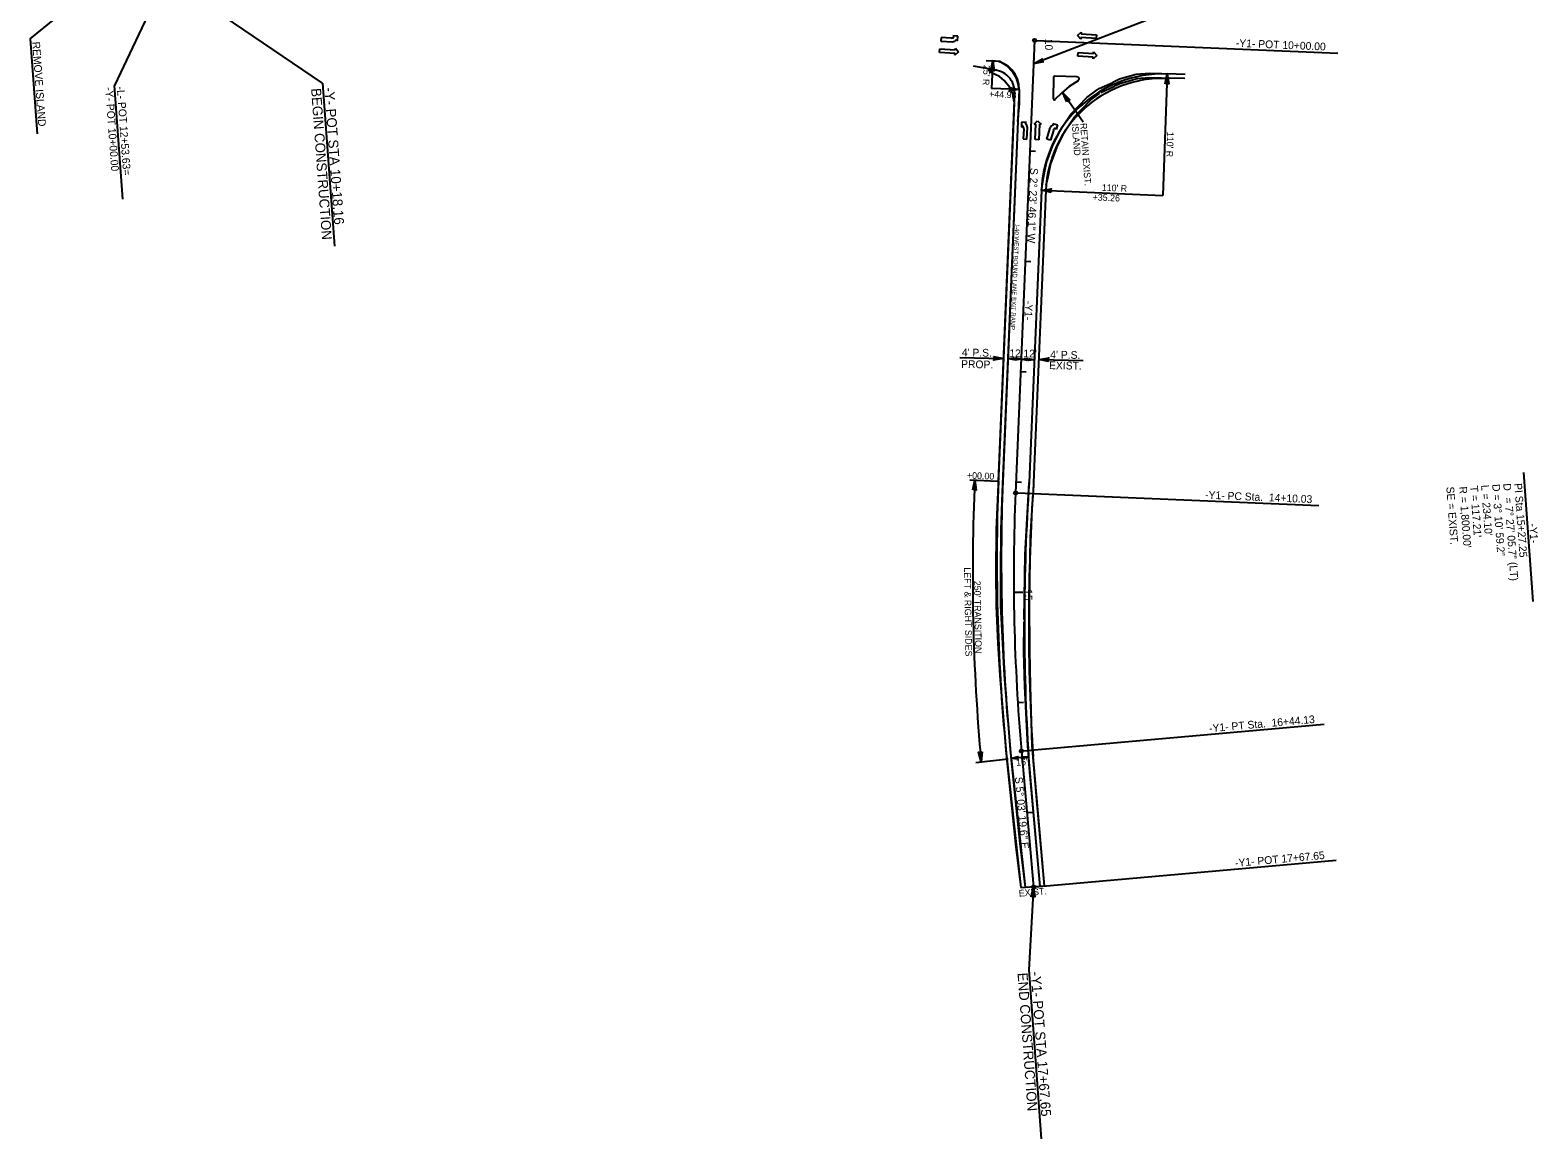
# Model space of a CAD drawing. Extents: x 2130900 to 2132500, y 642139 to 644213.
# Drawn here: x 2131135 to 2132500, y 642139 to 643143 of the extents above; entities that cross this region are included whole.
import ezdxf

# ---------------------------------------------------------------- set-up
doc = ezdxf.new("R2010")
doc.units = 0
for name, color, linetype in [('Old_Level_3', 7, 'Continuous'), ('Prop Dimension', 7, 'Continuous'), ('Prop Dimension Text', 7, 'Continuous'), ('Prop DSN Text', 7, 'Continuous'), ('Prop EOT', 7, 'Continuous'), ('Prop Horizontal Alignment', 7, 'Continuous'), ('Prop Horizontal Alignment Curve and Spiral Data', 7, 'Continuous'), ('Prop Horizontal Alignment Direction Label', 7, 'Continuous'), ('Prop Horizontal Alignment Station Label', 7, 'Continuous'), ('Prop Horizontal Alignment Tick Label', 7, 'Continuous'), ('Prop Horizontal Alignment Tick Large', 7, 'Continuous'), ('Prop Horizontal Alignment Tick Small', 7, 'Continuous'), ('Prop Paved Shoulder', 7, 'Continuous'), ('Prop Terminator CELL', 7, 'Continuous')]:
    doc.layers.add(name, color=color, linetype=linetype)

msp = doc.modelspace()

# ---------------------------------------------------------------- linework, layer by layer
at = {"layer": 'Old_Level_3'}
for p, q in [((2132009.6, 643106.9), (2131988.8, 643110.6)), ((2132012.7, 643114.9), (2132000.2, 643115.6)), ((2132004.4, 643104.9), (2132001.5, 643108.4)), ((2132019, 643110.8), (2132012.7, 643114.9)), ((2132024.6, 643105.2), (2132019, 643110.8)), ((2132012.3, 643101.3), (2132004.4, 643104.9)), ((2132016.6, 643097.8), (2132012.3, 643101.3)), ((2132021.9, 643091.3), (2132016.6, 643097.8)), ((2132027.8, 643099.9), (2132024.6, 643105.2)), ((2132029.4, 643094.6), (2132027.8, 643099.9)), ((2132030.4, 643088.1), (2132029.4, 643094.6)), ((2132061.2, 643100.6), (2132061, 643081.2)), ((2132082.6, 643101.1), (2132062.2, 643101.6)), ((2132075.6, 643092.1), (2132068.6, 643086.1)), ((2132083.6, 643097.4), (2132075.6, 643092.1)), ((2132102.7, 643090.5), (2132114.9, 643096)), ((2132104.3, 643086.8), (2132116.5, 643092.4)), ((2132121.2, 643098.8), (2132114.9, 643096)), ((2132122.8, 643095.1), (2132116.5, 643092.4)), ((2132136, 643103.1), (2132121.2, 643098.8)), ((2132137.1, 643099.3), (2132122.4, 643094.9)), ((2132148.3, 643104.1), (2132136, 643103.1)), ((2132148.6, 643100.2), (2132136.3, 643099.1)), ((2132159.3, 643103.7), (2132148.3, 643104.1)), ((2132159.2, 643099.7), (2132148.5, 643100.1)), ((2132180.3, 643099.4), (2132159.2, 643099.7)), ((2132180.4, 643103), (2132164.3, 643103.6)), ((2132024.6, 643085.7), (2132021.9, 643091.3)), ((2132025.7, 643078.4), (2132024.6, 643085.7)), ((2132026, 643086.4), (2132025, 643060.7)), ((2132030.6, 643076.8), (2132030.4, 643088.1)), ((2132068.6, 643086.1), (2132062.6, 643080.5)), ((2132077.1, 643067.1), (2132091.5, 643082.3)), ((2132080, 643064.4), (2132094.4, 643079.5)), ((2132091.5, 643082.3), (2132100.9, 643089.3)), ((2132093.9, 643079.1), (2132103.3, 643086.1)), ((2132100.9, 643089.3), (2132102.7, 643090.5)), ((2132026.6, 643076.7), (2132026.6, 643076.7)), ((2132029, 643060.5), (2132030.6, 643076.8)), ((2132068.6, 643054.4), (2132077.1, 643067.1)), ((2132072, 643052.2), (2132080.4, 643064.9)), ((2132025, 643060.7), (2132010.9, 642724.9)), ((2132029, 643060.5), (2132014.9, 642724.7)), ((2132026, 643060.7), (2132026, 643060.7)), ((2132060.5, 643038.1), (2132068.6, 643054.4)), ((2132064, 643036.3), (2132072.2, 643052.6)), ((2132055.1, 643023.5), (2132060.5, 643038.1)), ((2132052.1, 643009.8), (2132055.1, 643023.5)), ((2132058.9, 643022.2), (2132064.2, 643036.7)), ((2132050.4, 642998.1), (2132052.1, 643009.8)), ((2132056.1, 643008.9), (2132059, 643022.7)), ((2132050.4, 642998.2), (2132039.3, 642733.7)), ((2132054.6, 643003), (2132056.1, 643009.1)), ((2132010.9, 642724.9), (2132009.5, 642690.7)), ((2132014.9, 642724.7), (2132013.5, 642690.7)), ((2132035.7, 642668.2), (2132039.3, 642733.7)), ((2132040.6, 642684), (2132042.9, 642723.5)), ((2132043.3, 642733.6), (2132042.9, 642723.5)), ((2132009.5, 642690.8), (2132009.2, 642652.1)), ((2132013.5, 642690.7), (2132013.2, 642652.1)), ((2132039.7, 642625.1), (2132040.6, 642684)), ((2132034.8, 642609.5), (2132035.7, 642668.4)), ((2132009.2, 642652.1), (2132009.3, 642622.1)), ((2132013.2, 642652.1), (2132013.3, 642622.1)), ((2132009.3, 642621.9), (2132011, 642587.7)), ((2132013.3, 642622.1), (2132015, 642587.9)), ((2132039.9, 642581.6), (2132039.7, 642625.2)), ((2132034.5, 642580.2), (2132034.8, 642607.3)), ((2132011, 642587.7), (2132012.7, 642558.8)), ((2132015, 642587.9), (2132016.7, 642559.1)), ((2132035.3, 642548.7), (2132034.5, 642580.2)), ((2132040.5, 642549.2), (2132039.9, 642581.6)), ((2132012.7, 642558.8), (2132015.9, 642517.8)), ((2132016.7, 642559.1), (2132019.9, 642518.1)), ((2132038, 642494.8), (2132035.3, 642548.7)), ((2132042, 642494.9), (2132040.5, 642549.3)), ((2132015.9, 642517.8), (2132018.6, 642484.9)), ((2132019.9, 642518.1), (2132022.6, 642485.2)), ((2132042.6, 642442.4), (2132038, 642494.8)), ((2132046.6, 642442.7), (2132042, 642495.1)), ((2132018.6, 642484.8), (2132026.9, 642406.2)), ((2132022.6, 642485.2), (2132030.9, 642406.6)), ((2132049.2, 642367.8), (2132042.6, 642442.4)), ((2132053.2, 642368.2), (2132046.6, 642442.7)), ((2132026.9, 642406.1), (2132031.7, 642366.7)), ((2132030.9, 642406.6), (2132035.7, 642367.2))]:
    msp.add_line(p, q, dxfattribs=at)
for centre, radius, start, end in [((2132062.2, 643100.6), 1, 88.471, 179.2281), ((2132082.5, 643099.1), 2, 303.1072, 88.471), ((2132062, 643081.2), 1, 179.2281, 313.269)]:
    msp.add_arc(centre, radius, start, end, dxfattribs=at)
at = {"layer": 'Prop Dimension'}
for p, q in [((2132164.3, 643103.6), (2132160.3, 642993.6)), ((2132050.4, 642998.2), (2132160.3, 642993.6)), ((2131976.6, 642846.8), (2132016, 642845.9)), ((2132032, 642845.3), (2132020, 642845.8)), ((2132044, 642844.8), (2132032, 642845.3)), ((2132048, 642845.1), (2132088.3, 642844.2)), ((2131985.4, 642736), (2132010.6, 642734.9)), ((2131991.1, 642480.1), (2132020.2, 642483.3))]:
    msp.add_line(p, q, dxfattribs=at)
msp.add_arc((2133825.3, 642648.9), 1837.2, 177.2909, 185.2561, dxfattribs=at)
at = {"layer": 'Prop Dimension Text'}
for p, q in [((2131399.3, 643095.3), (2131250.2, 643196.6)), ((2131399.3, 643095.3), (2131410.1, 642947.7)), ((2132020, 642845.8), (2132032, 642845.3)), ((2132032, 642845.3), (2132044, 642844.8))]:
    msp.add_line(p, q, dxfattribs=at)
for points in [[(2132153.8, 643307.6), (2132164.7, 643159.4), (2132043.2, 643112.7)], [(2132043.2, 642367.3), (2132039, 642292.2), (2132050.1, 642139.2)]]:
    msp.add_lwpolyline(points, dxfattribs=at)
at = {"layer": 'Prop DSN Text'}
for p, q in [((2131134.6, 643135.3), (2131224.5, 643208.3)), ((2131134.6, 643135.3), (2131140.9, 643049.4)), ((2132006.4, 643115.5), (2132005.2, 643090.5)), ((2132030.2, 643089.4), (2132005.2, 643090.5)), ((2132088.2, 643059.8), (2132069.6, 643086.6)), ((2132038.8, 642485), (2132022.9, 642483.6))]:
    msp.add_line(p, q, dxfattribs=at)
at = {"layer": 'Prop EOT'}
for p, q in [((2132030.2, 643089.4), (2132015.3, 642734.7)), ((2132050.4, 642998.1), (2132039.3, 642733.7)), ((2132050.4, 642998.2), (2132050.4, 642998.1)), ((2132022.9, 642483.6), (2132035.7, 642367.2)), ((2132049.2, 642367.8), (2132038.8, 642485)), ((2132031.7, 642366.7), (2132053.2, 642368.2))]:
    msp.add_line(p, q, dxfattribs=at)
for centre, radius, start, end in [((2132005.2, 643090.5), 25, 357.6039, 87.1626), ((2132160.3, 642993.6), 110, 87.9196, 177.6039), ((2133832.7, 642663.7), 1818.7, 177.7625, 185.6837), ((2133908.3, 642605.7), 1873.4, 176.0817, 183.6939)]:
    msp.add_arc(centre, radius, start, end, dxfattribs=at)
at = {"layer": 'Prop Horizontal Alignment'}
for p, q in [((2132044.1, 643133.9), (2132026.9, 642724.2)), ((2132032.3, 642490.3), (2132043.2, 642367.3))]:
    msp.add_line(p, q, dxfattribs=at)
msp.add_arc((2133825.3, 642648.9), 1800, 177.6039, 185.0554, dxfattribs=at)
at = {"layer": 'Prop Horizontal Alignment Curve and Spiral Data'}
msp.add_line((2132486.9, 642742.5), (2132495.4, 642625.8), dxfattribs=at)
at = {"layer": 'Prop Horizontal Alignment Station Label'}
for p, q in [((2131250.8, 643177.2), (2131211.1, 643093.2)), ((2132045.6, 643133.8), (2132318.8, 643122.4)), ((2131218.6, 642990.3), (2131211.1, 643093.2)), ((2132028.4, 642724.1), (2132301.7, 642712.7)), ((2132033.8, 642490.5), (2132306.3, 642514.6)), ((2132044.7, 642367.4), (2132317.2, 642391.5))]:
    msp.add_line(p, q, dxfattribs=at)
for centre in [(2132044.1, 643133.9), (2132026.9, 642724.2), (2132032.3, 642490.3), (2132043.2, 642367.3)]:
    msp.add_circle(centre, 1.5, dxfattribs=at)
at = {"layer": 'Prop Horizontal Alignment Tick Large'}
for p, q in [((2132044.1, 643133.9), (2132052.1, 643133.5)), ((2132025.4, 642634.3), (2132033.4, 642634.3))]:
    msp.add_line(p, q, dxfattribs=at)
at = {"layer": 'Prop Horizontal Alignment Tick Small'}
for p, q in [((2132039.9, 643034), (2132044.9, 643033.8)), ((2132035.7, 642934), (2132040.7, 642933.8)), ((2132031.5, 642834.1), (2132036.5, 642833.9)), ((2132027.3, 642734.2), (2132032.3, 642734)), ((2132029, 642534.3), (2132034, 642534.6)), ((2132037.3, 642434.7), (2132042.2, 642435.1))]:
    msp.add_line(p, q, dxfattribs=at)
at = {"layer": 'Prop Paved Shoulder'}
for p, q in [((2132006.4, 643115.5), (2132006.3, 643107.2)), ((2132164.3, 643103.6), (2132164.1, 643099.6)), ((2132026.1, 643086.4), (2132011.3, 642734.9)), ((2132054.4, 642998.1), (2132043.3, 642733.6)), ((2132018.9, 642483.2), (2132031.7, 642366.7)), ((2132053.2, 642368.2), (2132042.8, 642485.4))]:
    msp.add_line(p, q, dxfattribs=at)
for centre, radius, start, end in [((2132006.1, 643087.2), 20, 357.747, 89.2185), ((2132160.3, 642993.6), 106, 87.9196, 177.6039), ((2133832.7, 642663.7), 1822.7, 177.7625, 185.6837), ((2133907.9, 642605.7), 1869, 176.081, 183.6915)]:
    msp.add_arc(centre, radius, start, end, dxfattribs=at)
at = {"layer": 'Prop Terminator CELL'}
for p, q in [((2131959.5, 643136.7), (2131959.3, 643133.4)), ((2131959.3, 643133.4), (2131969.8, 643132.7)), ((2131968.6, 643136.1), (2131959.5, 643136.7)), ((2131974.7, 643137.9), (2131970.2, 643138.2)), ((2131970.2, 643138.2), (2131971.2, 643137.1)), ((2131973.4, 643134.6), (2131974.4, 643133.5)), ((2131974.4, 643133.5), (2131974.7, 643137.9)), ((2132083, 643138.4), (2132086.3, 643141.3)), ((2132085.9, 643135.1), (2132083, 643138.4)), ((2132086, 643136.6), (2132085.9, 643135.1)), ((2132099.9, 643135.8), (2132086, 643136.6)), ((2132086.3, 643141.3), (2132086.2, 643139.9)), ((2132086.2, 643139.9), (2132100.1, 643139)), ((2132100.1, 643139), (2132099.9, 643135.8)), ((2131958.2, 643123), (2131958.4, 643126.3)), ((2131972.2, 643122.1), (2131958.2, 643123)), ((2131958.4, 643126.3), (2131972.4, 643125.4)), ((2131975.4, 643123.5), (2131972.1, 643120.6)), ((2131972.1, 643120.6), (2131972.2, 643122.1)), ((2131972.4, 643125.4), (2131972.5, 643126.8)), ((2131972.5, 643126.8), (2131975.4, 643123.5)), ((2132083.2, 643119.7), (2132083.5, 643123)), ((2132097.2, 643118.8), (2132083.2, 643119.7)), ((2132083.5, 643123), (2132097.4, 643122.1)), ((2132100.5, 643120.3), (2132097.1, 643117.3)), ((2132097.4, 643122.1), (2132097.5, 643123.6)), ((2132097.5, 643123.6), (2132100.5, 643120.3)), ((2132097.1, 643117.3), (2132097.2, 643118.8)), ((2132032.4, 643059.8), (2132032.2, 643055.4)), ((2132032.2, 643055.4), (2132033.3, 643056.4)), ((2132036.8, 643059.6), (2132032.4, 643059.8)), ((2132034.3, 643053.8), (2132033.9, 643044.7)), ((2132035.7, 643058.6), (2132036.8, 643059.6)), ((2132037.2, 643044.5), (2132037.7, 643055.1)), ((2132043.7, 643058.2), (2132046.9, 643061.2)), ((2132045.2, 643058.2), (2132043.7, 643058.2)), ((2132044.6, 643044.2), (2132045.2, 643058.2)), ((2132046.9, 643061.2), (2132050, 643058)), ((2132048.5, 643058), (2132047.9, 643044)), ((2132050, 643058), (2132048.5, 643058)), ((2132055.4, 643044.6), (2132058.4, 643054.8)), ((2132061.2, 643052.5), (2132058.6, 643043.7)), ((2132061.4, 643057.5), (2132060.7, 643058.8)), ((2132060.7, 643058.8), (2132064.9, 643057.6)), ((2132063.7, 643053.3), (2132063, 643054.6)), ((2132064.9, 643057.6), (2132063.7, 643053.3)), ((2132033.9, 643044.7), (2132037.2, 643044.5)), ((2132047.9, 643044), (2132044.6, 643044.2)), ((2132058.6, 643043.7), (2132055.4, 643044.6))]:
    msp.add_line(p, q, dxfattribs=at)
for points in [[(2132004.5, 643106.5), (2132006.4, 643115.5), (2132007.6, 643106.3), (2132006.1, 643107.6)], [(2132052.1, 643114.5), (2132043.2, 643112.7), (2132051, 643117.4), (2132050.5, 643115.5)], [(2132162.4, 643094.6), (2132164.3, 643103.6), (2132165.6, 643094.5), (2132164, 643095.7)], [(2132021.3, 643091.4), (2132030.2, 643089.4), (2132021.1, 643088.2), (2132022.3, 643089.8)], [(2132073.5, 643078.3), (2132069.6, 643086.6), (2132076.1, 643080.1), (2132074.1, 643080.1)], [(2132059.3, 642996.3), (2132050.4, 642998.2), (2132059.5, 642999.5), (2132058.3, 642997.9)], [(2132007, 642847.6), (2132016, 642845.9), (2132006.9, 642844.5), (2132008.1, 642846)], [(2132025.3, 642844.6), (2132020, 642845.8), (2132025.5, 642846.5), (2132024.7, 642845.6)], [(2132026.6, 642846.4), (2132032, 642845.3), (2132026.5, 642844.5), (2132027.2, 642845.5)], [(2132037.3, 642844.1), (2132032, 642845.3), (2132037.4, 642846), (2132036.7, 642845.1)], [(2132038.6, 642845.9), (2132044, 642844.8), (2132038.5, 642844), (2132039.2, 642845)], [(2132056.9, 642843.2), (2132048, 642845.1), (2132057.1, 642846.4), (2132055.9, 642844.8)], [(2131988.2, 642726.9), (2131990.2, 642735.8), (2131991.4, 642726.7), (2131989.8, 642727.9)], [(2131996.6, 642489.7), (2131995.9, 642480.6), (2131993.5, 642489.5), (2131995.2, 642488.5)], [(2132029.3, 642483.1), (2132022.9, 642483.6), (2132029.1, 642485.3), (2132028.4, 642484.1)], [(2132032.5, 642485.5), (2132038.8, 642485), (2132032.6, 642483.3), (2132033.3, 642484.5)], [(2132041.2, 642358.4), (2132043.2, 642367.3), (2132044.3, 642358.2), (2132042.8, 642359.4)]]:
    msp.add_lwpolyline(points, close=True, dxfattribs=at)
for centre, radius, start, end in [((2131968.9, 643139.4), 3.27, 266.168, 315.8262), ((2131969.4, 643138), 5.25, 274.8441, 320.1558), ((2132031.1, 643054), 3.27, 357.6039, 47.262), ((2132032.5, 643054.5), 5.25, 6.2799, 51.5916), ((2132063.1, 643052.6), 5.25, 109.7263, 155.038), ((2132064.3, 643051.6), 3.27, 114.0559, 163.7141)]:
    msp.add_arc(centre, radius, start, end, dxfattribs=at)

# ---------------------------------------------------------------- texts
at = {"layer": 'Old_Level_3'}
msp.add_text('I-40 WEST BOUND LANE EXIT RAMP ', height=4, rotation=267.4631, dxfattribs=at).set_placement((2132026.5, 642967.5))
at = {"layer": 'Prop Dimension Text'}
for s, height, rotation, p in [('REMOVE ISLAND', 7, 274.1431, (2131136.5, 643132.6)), ("25' R", 6, 267.1626, (2131998, 643111.9)), ('BEGIN CONSTRUCTION', 9, 274.1585, (2131389, 643090.4)), ('-Y- POT STA 10+18.16', 9, 274.1585, (2131401, 643091.2)), ('+44.98', 6, 357.6039, (2132002.9, 643082.5)), ('ISLAND', 6, 274.1431, (2132077.9, 643058.3)), ('RETAIN EXIST.', 6, 274.1431, (2132085.4, 643058.9)), ("110' R", 6, 267.9196, (2132164.2, 643051.3)), ("110' R", 6, 357.6039, (2132104.9, 642997.8)), ('+35.26', 6, 357.6039, (2132096.6, 642989.1)), ("4' P.S.", 7, 358.9432, (2131978.2, 642848)), ("12'", 7, 358.9432, (2132021.2, 642847.2)), ("12'", 7, 358.9432, (2132034, 642847)), ("4' P.S.", 7, 358.9432, (2132058.3, 642846)), ('PROP.', 7, 358.9432, (2131977.6, 642837.4)), ('EXIST.', 7, 358.9432, (2132057.2, 642836.3)), ('+00.00', 6, 357.6039, (2131982.8, 642737.2)), ('LEFT & RIGHT SIDES', 6, 270.9427, (2131980.3, 642656.7)), ("250' TRANSITION", 6, 270.9427, (2131989.3, 642644.5)), ("16'", 6, 5.0554, (2132027.7, 642476.9)), ('EXIST.', 6, 5.0554, (2132030.1, 642358.5)), ('END CONSTRUCTION', 9, 274.1585, (2132028.7, 642289.3)), ('-Y1- POT STA 17+67.65', 9, 274.1585, (2132040.7, 642290.2))]:
    msp.add_text(s, height=height, rotation=rotation, dxfattribs=at).set_placement(p)
at = {"layer": 'Prop Horizontal Alignment Curve and Spiral Data'}
for s, p in [('SE = EXIST.', (2132417, 642729.6)), ("R = 1,800.00'", (2132428.6, 642729.7)), ("T = 117.21'", (2132438.6, 642730.4)), ("L = 234.10'", (2132448.5, 642731.2)), ('D = 3%%d 10\' 59.2"', (2132458.5, 642731.9)), ('D', (2132468.5, 642732.6)), ('PI Sta 15+27.25', (2132478.5, 642732.7)), ('= 7%%d 27\' 05.7" (LT)', (2132469.7, 642719.8))]:
    msp.add_text(s, height=7, rotation=274.1431, dxfattribs=at).set_placement(p)
at = {"layer": 'Prop Horizontal Alignment Direction Label'}
for s, rotation, p in [('S 2%%d 23\' 46.1" W', 267.6039, (2132040.3, 643018.6)), ('-Y1-', 267.6039, (2132035.6, 642898.2)), ('-Y1-', 274.1431, (2132492, 642696.1)), ('S 5%%d 03\' 19.6" E', 275.0554, (2132026.3, 642466.7))]:
    msp.add_text(s, height=7, rotation=rotation, dxfattribs=at).set_placement(p)
at = {"layer": 'Prop Horizontal Alignment Station Label'}
for s, rotation, p in [('-Y1- POT 10+00.00', 357.6039, (2132226.3, 643128.2)), ('-L- POT 12+53.63=', 274.1431, (2131213.1, 643092)), ('-Y- POT 10+00.00', 274.1431, (2131202.6, 643091.3)), ('-Y1- PC Sta.  14+10.03', 357.6039, (2132198.5, 642719)), ('-Y1- PT Sta.  16+44.13', 5.0554, (2132202.5, 642507.4)), ('-Y1- POT 17+67.65', 5.0554, (2132226, 642385.5))]:
    msp.add_text(s, height=7, rotation=rotation, dxfattribs=at).set_placement(p)
at = {"layer": 'Prop Horizontal Alignment Tick Label'}
for s, rotation, p in [('10', 267.6039, (2132053.9, 643135.6)), ('15', 270.4676, (2132035, 642637))]:
    msp.add_text(s, height=7, rotation=rotation, dxfattribs=at).set_placement(p)

doc.saveas('drawing.dxf')
